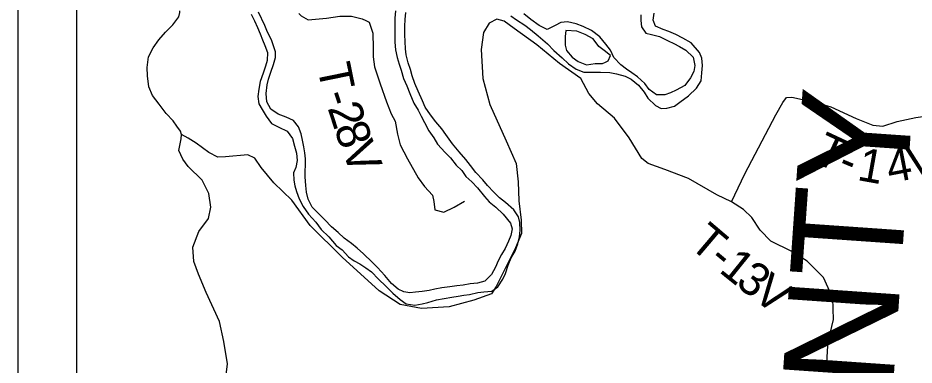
# Model space of a CAD drawing. Extents: x -84548 to 2262448, y -162180 to 525962.
# Drawn here: x -37475 to -29387, y 150992 to 154121 of the extents above; entities that cross this region are included whole.
import ezdxf

# ---------------------------------------------------------------- set-up
doc = ezdxf.new("R2010")
doc.units = 0
for name, color, linetype in [('GM_X_City_Street_Text', 7, 'Continuous'), ('GM_X_County', 7, 'Continuous'), ('GM_X_Interstate_Location', 7, 'Continuous'), ('GM_X_Minor_Lake', 7, 'Continuous'), ('GM_X_Minor_River_Text', 7, 'Continuous'), ('GM_X_Township_Road', 7, 'Continuous')]:
    doc.layers.add(name, color=color, linetype=linetype)

msp = doc.modelspace()

# ---------------------------------------------------------------- linework, layer by layer
at = {"layer": 'GM_X_County'}
for p, q in [((-37474.5, 167015.5), (-37474.5, 130055.5)), ((-36946.5, 166487.5), (-36946.5, 130583.5)), ((-36946.5, 166487.5), (-36946.5, 130583.5))]:
    msp.add_line(p, q, dxfattribs=at)
at = {"layer": 'GM_X_Interstate_Location'}
for points in [[(-35369.1, 154154.9), (-35339, 154094.8), (-35313, 154034.7), (-35287, 153976.5), (-35267, 153924.4), (-35245, 153872.3), (-35223, 153810.2), (-35225.1, 153736.1), (-35241.2, 153686), (-35261.3, 153621.9), (-35287.5, 153547.8), (-35301.6, 153479.6), (-35309.7, 153413.5), (-35299.7, 153345.4), (-35269.7, 153295.3), (-35235.7, 153235.1), (-35187.6, 153169), (-35119.5, 153136.9), (-35045.3, 153100.7), (-34997.3, 153034.6), (-34977.3, 152966.4), (-34961.3, 152902.3), (-34955.4, 152836.2), (-34967.5, 152774.1), (-34987.6, 152724), (-34985.6, 152659.9), (-34975.7, 152607.8), (-34961.7, 152557.7), (-34937.7, 152491.5), (-34899.7, 152421.4), (-34853.6, 152353.2), (-34787.5, 152281), (-34737.5, 152214.8), (-34669.4, 152148.7), (-34601.3, 152070.5), (-34547.2, 152030.4), (-34491.1, 151968.2), (-34441, 151930.1), (-34388.9, 151904), (-34334.8, 151867.9), (-34284.8, 151831.8), (-34220.7, 151765.6), (-34154.6, 151701.4), (-34090.5, 151639.3), (-34026.4, 151583.1), (-33970.3, 151545), (-33892.1, 151530.9), (-33825.9, 151544.9), (-33775.8, 151556.9), (-33695.6, 151580.9), (-33627.4, 151592.8), (-33559.2, 151604.8), (-33501.1, 151612.8), (-33448.9, 151620.7), (-33398.8, 151628.7), (-33324.6, 151644.7), (-33268.5, 151650.7), (-33196.3, 151658.6), (-33142.1, 151696.7), (-33097.9, 151764.8), (-33075.8, 151816.8), (-33051.7, 151891), (-33023.5, 151959.1), (-32987.4, 152019.2), (-32963.3, 152085.3), (-32947.2, 152147.4)], [(-33095.3, 152351.9), (-33029.3, 152271.7), (-33013.3, 152219.5), (-33027.4, 152159.4), (-33047.5, 152109.4), (-33077.6, 152043.3), (-33109.7, 151989.2), (-33139.9, 151931.1), (-33166, 151875), (-33202.1, 151808.9), (-33260.3, 151746.8), (-33326.5, 151730.9), (-33392.7, 151722.9), (-33456.9, 151710.9), (-33515, 151705), (-33577.2, 151697), (-33649.4, 151687), (-33711.5, 151675), (-33763.7, 151663.1), (-33827.8, 151655.1), (-33888, 151649.1), (-33938.1, 151643.2), (-33992.2, 151651.2), (-34044.3, 151675.3), (-34102.4, 151727.4), (-34164.5, 151797.6), (-34230.6, 151869.8), (-34278.7, 151919.9), (-34356.8, 151994.1), (-34412.9, 152044.3), (-34464.9, 152086.4), (-34529, 152134.5), (-34585.1, 152186.7), (-34643.2, 152238.8), (-34703.3, 152301), (-34755.4, 152351.1), (-34819.5, 152415.3), (-34855.5, 152487.4), (-34871.5, 152549.6), (-34877.4, 152611.7), (-34881.3, 152689.8), (-34881.3, 152739.9), (-34879.2, 152794), (-34879.2, 152852.1), (-34885.1, 152906.3), (-34895.1, 152960.4), (-34907.1, 153020.5), (-34919, 153076.6), (-34943, 153140.7), (-34987.1, 153194.9), (-35053.2, 153227), (-35125.4, 153253.1), (-35193.5, 153297.2), (-35227.5, 153365.4), (-35233.5, 153439.5), (-35225.4, 153517.6), (-35213.3, 153567.7), (-35191.2, 153631.8), (-35169, 153701.9), (-35148.9, 153764), (-35150.9, 153816.1), (-35166.8, 153870.3), (-35184.8, 153924.4), (-35220.9, 153992.5), (-35246.9, 154052.6), (-35302.9, 154172.9)], [(-34067.8, 154184), (-34071.9, 154117.9), (-34074, 154063.8), (-34074.1, 153901.5), (-34066.2, 153833.3), (-34052.2, 153765.2), (-34034.2, 153705.1), (-34016.3, 153649), (-33994.3, 153574.8), (-33966.3, 153508.7), (-33938.3, 153438.5), (-33902.3, 153352.3), (-33862.2, 153288.2), (-33836.2, 153234.1), (-33806.2, 153177.9), (-33766.2, 153103.8), (-33720.2, 153041.6), (-33688.1, 152983.5), (-33620, 152909.3), (-33572, 152859.2), (-33519.9, 152795), (-33469.8, 152746.9), (-33433.8, 152692.7), (-33379.7, 152644.6), (-33327.7, 152588.5), (-33263.6, 152512.3), (-33221.5, 152462.2), (-33161.4, 152414), (-33095.3, 152351.9)], [(-32947.2, 152147.4), (-32941.1, 152207.5), (-32945, 152277.6), (-32957, 152327.7), (-32999.1, 152391.9), (-33075.2, 152456), (-33129.3, 152500.2), (-33179.3, 152550.3), (-33237.4, 152610.4), (-33277.5, 152660.6), (-33341.5, 152726.7), (-33391.6, 152790.9), (-33431.6, 152845), (-33491.7, 152915.2), (-33551.8, 152987.4), (-33611.9, 153069.6), (-33649.9, 153121.7), (-33704, 153183.9), (-33752, 153246), (-33800.1, 153316.2), (-33824.1, 153372.3), (-33862.1, 153460.5), (-33894.1, 153528.7), (-33916.1, 153598.8), (-33932, 153656.9), (-33954, 153715), (-33970, 153787.2), (-33976, 153843.3), (-33979.9, 153907.4), (-33981.9, 153967.5), (-33981.8, 154047.7), (-33979.7, 154107.8), (-33973.6, 154169.9)], [(-33025.3, 154141.1), (-32975.2, 154103), (-32899.1, 154054.9), (-32849, 154016.8), (-32778.9, 153958.6), (-32696.8, 153888.4), (-32638.7, 153826.2), (-32562.6, 153762.1), (-32506.5, 153705.9), (-32436.4, 153657.8), (-32366.2, 153631.7), (-32286.1, 153631.6), (-32217.9, 153633.6), (-32133.7, 153629.5), (-32071.5, 153617.4), (-31995.4, 153597.3), (-31939.3, 153569.3), (-31873.2, 153515.1), (-31823.1, 153450.9), (-31789.1, 153398.8), (-31721, 153330.6), (-31668.9, 153304.6), (-31618.8, 153306.5), (-31550.6, 153326.5), (-31500.4, 153360.5), (-31424.2, 153418.6), (-31351.9, 153486.7), (-31309.8, 153554.7), (-31303.7, 153624.9), (-31297.6, 153691), (-31303.5, 153759.1), (-31323.5, 153809.2), (-31399.6, 153895.4), (-31473.8, 153939.6), (-31537.9, 153971.7), (-31600, 153999.8), (-31652.1, 154017.9), (-31720.2, 154048), (-31742.2, 154102.1), (-31732.2, 154164.2)], [(-31852.5, 154150.3), (-31854.5, 154098.2), (-31846.6, 154040), (-31806.5, 153983.9), (-31756.4, 153971.8), (-31684.3, 153953.8), (-31606.1, 153913.6), (-31556, 153889.6), (-31503.9, 153863.5), (-31447.8, 153831.4), (-31381.7, 153767.2), (-31365.7, 153691), (-31375.8, 153639), (-31406, 153580.9), (-31456.2, 153512.8), (-31534.4, 153468.8), (-31584.5, 153444.7), (-31636.7, 153426.8), (-31712.9, 153428.8), (-31777, 153477), (-31817, 153529.1), (-31883.1, 153591.3), (-31933.2, 153627.4), (-31983.3, 153659.4), (-32033.4, 153697.6), (-32095.5, 153763.7), (-32127.5, 153831.9), (-32167.5, 153886), (-32223.6, 153950.2), (-32299.7, 154006.3), (-32373.8, 154042.4), (-32438, 154068.5), (-32514.1, 154086.6), (-32576.3, 154078.7), (-32626.4, 154052.7), (-32698.7, 154016.6), (-32770.8, 154052.8), (-32846.9, 154106.9), (-32909, 154159.1)], [(-32530.8, 154008.6), (-32536.7, 153954.5), (-32536.6, 153876.4), (-32524.6, 153826.4), (-32472.5, 153768.4), (-32418.5, 153728.4), (-32344.4, 153698.5), (-32266.4, 153710.6), (-32198.4, 153710.7), (-32171.5, 153722.1)], [(-32171.5, 153722.1), (-32146.5, 153732.8), (-32126.5, 153782.9), (-32182.6, 153828.9), (-32232.6, 153864.8), (-32284.7, 153932.8), (-32354.7, 153972.8), (-32430.8, 154000.7), (-32530.8, 154008.6)]]:
    msp.add_lwpolyline(points, dxfattribs=at)
at = {"layer": 'GM_X_Minor_Lake'}
for points in [[(-34939.3, 154162.2), (-34919.2, 154140.8), (-34856.1, 154104.2), (-34689.9, 154118.2), (-34570, 154137.2), (-34463.7, 154135.8), (-34368.8, 154112), (-34335, 154097.2)], [(-30173.5, 150977.2), (-30170, 151125.4), (-30158.3, 151213.5), (-30114.9, 151403.8), (-30119.6, 151595.9), (-30204.2, 151779.9), (-30350.8, 151927.7), (-30491.2, 152015.4), (-30679.6, 152109), (-30776, 152208.9), (-30852.5, 152322.8), (-30926.7, 152394.6), (-31035, 152464.4), (-31167.3, 152526.2), (-31424, 152673.7), (-31636.4, 152755.2), (-31786.7, 152808.9), (-31844.8, 152852.8), (-31957.5, 153040.7), (-32092.2, 153218.5), (-32242.7, 153346.3), (-32321.1, 153440.1), (-32395.6, 153574.1), (-32586.2, 153711.7), (-32790.9, 153877.4), (-32995.5, 154025), (-33085.8, 154090.8), (-33153.9, 154110.7), (-33221.8, 154074.5), (-33271.5, 153990.3), (-33293, 153836.1), (-33280.1, 153575.9), (-33215.3, 153339.9), (-33068.1, 153011.9), (-32979.4, 152809.9), (-32960.8, 152643.8), (-32954.2, 152471.7), (-32931.6, 152297.6), (-32931.2, 152177.5), (-32984.8, 152049.2), (-33157.8, 151698.5), (-33199.6, 151634.3), (-33359.5, 151575.9), (-33581.4, 151517.3), (-33831.5, 151502.7), (-34023.8, 151536.2), (-34214.3, 151661.9), (-34547.5, 151963.3), (-34838.6, 152248.9), (-35003.5, 152478.7), (-35164.1, 152634.4), (-35280.7, 152772.3), (-35337, 152856.2), (-35401.1, 152886.1), (-35601.2, 152867.6), (-35669.2, 152865.4), (-35751.4, 152909.2), (-35865.8, 152993), (-35938, 153036.9), (-35998.1, 153070.8)], [(-34335, 154097.2), (-34333.8, 154096.6), (-34303.9, 154083.5), (-34271.3, 153984), (-34270, 153849.6), (-34270.1, 153769.4), (-34257.9, 153681.4), (-34205.9, 153528.2), (-34147.7, 153363.2), (-34106.9, 153255.8), (-34069.2, 153190.6), (-34048.2, 153072.7), (-34025.8, 152977), (-33958.5, 152850.2), (-33864, 152680), (-33803.9, 152601.3), (-33733.7, 152522.7), (-33720.3, 152464.9), (-33712.4, 152390.8), (-33631.7, 152370.7), (-33536.5, 152415.2), (-33445.5, 152469.5)], [(-31035, 152464.4), (-30913.8, 152715), (-30635.4, 153246.1), (-30571.8, 153358.4), (-30539.9, 153402.5), (-30489.9, 153406.7), (-30271.6, 153359.1), (-30137.4, 153319.4), (-29908.9, 153215.9), (-29758.6, 153154.2), (-29668.5, 153144.5), (-29540.6, 153186.8), (-29372.6, 153223.3), (-29182.6, 153249.8), (-29024.1, 153332.6)]]:
    msp.add_lwpolyline(points, dxfattribs=at)
at = {"layer": 'GM_X_Minor_River_Text'}
for points in [[(-36201.2, 153342.5), (-36261.5, 153420.4), (-36293.7, 153498.4), (-36304.1, 153598.5), (-36308.3, 153674.5), (-36296.7, 153770.7), (-36252.9, 153850.8), (-36203.1, 153925), (-36143.3, 153993.2), (-36077.5, 154059.4), (-36023.7, 154131.6), (-36012.4, 154171), (-36012.3, 154185.1)], [(-35998.1, 153070.8), (-36008.2, 153100.8), (-36039.2, 153146), (-36072.6, 153194.7), (-36136.9, 153260.6), (-36201.2, 153342.5)], [(-35604.3, 150827.7), (-35582.9, 151001.9), (-35617.6, 151204), (-35654.2, 151384.1), (-35775.2, 151646), (-35845.8, 151810), (-35886.2, 151926), (-35894.6, 152054.1), (-35843.1, 152194.3), (-35755.4, 152312.7), (-35733.8, 152414.8), (-35750.2, 152538.9), (-35810.6, 152658.9), (-35937.1, 152780.7), (-35987.4, 152848.6), (-36021.7, 152926.6), (-36000, 153030.7), (-35998.1, 153070.8)]]:
    msp.add_lwpolyline(points, dxfattribs=at)

# ---------------------------------------------------------------- texts
at = {"layer": 'GM_X_City_Street_Text'}
msp.add_text('VINTON  COUNTY', height=1000, rotation=86.01767, dxfattribs=at).set_placement((-30187.2, 142028.3))
at = {"layer": 'GM_X_Township_Road'}
for s, rotation, p in [('T', 281.52931, (-34774.5, 153683.7)), ('-', 288.1676, (-34719.9, 153427.3)), ('2', 287.95443, (-34681.6, 153310.5)), ('8', 288.2807, (-34624.1, 153132.9)), ('T', 335.0336, (-30307.1, 152828.6)), ('V', 291.98766, (-34558.8, 152937.6)), ('V', 12.38057, (-29418.4, 152666.4)), ('1', 349.86315, (-29909.4, 152661.1)), ('4', 11.03289, (-29607.3, 152629.5)), ('-', 337.375, (-30091.4, 152728.5)), ('T', 319.64788, (-31429.2, 152066.7)), ('-', 320.14402, (-31256.1, 151919.5)), ('1', 321.13696, (-31157.1, 151837)), ('3', 322.07074, (-31009.1, 151717.8)), ('V', 323.34243, (-30857.6, 151599.7))]:
    msp.add_text(s, height=300, rotation=rotation, dxfattribs=at).set_placement(p)

doc.saveas('drawing.dxf')
